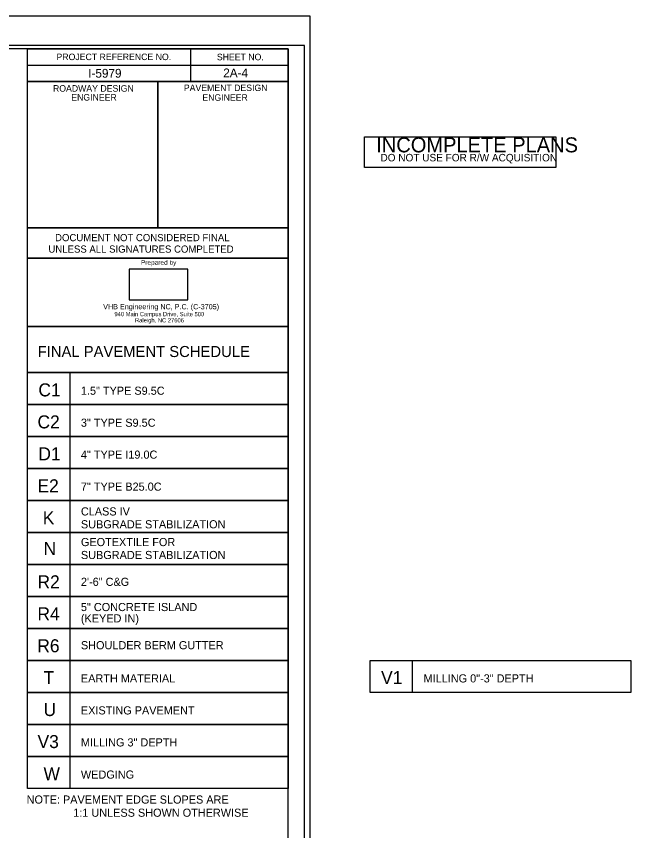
# Model space of a CAD drawing. Extents: x 573748 to 574632, y -54663 to -53209.
# Drawn here: x 574235.8 to 574330.2, y -54038.9 to -53913.7 of the extents above; entities that cross this region are included whole.
import ezdxf

# ---------------------------------------------------------------- set-up
doc = ezdxf.new("R2010")
doc.units = 0
for name, color, linetype in [('Default', 7, 'Continuous'), ('Prop Pavement Schedule Description CELL', 7, 'Continuous'), ('Sheet Cutting Line CELL', 7, 'Continuous'), ('Sheet Data Field CELL', 7, 'Continuous'), ('Sheet Plan CELL', 7, 'Continuous'), ('Sheet Plot Border Inside CELL', 7, 'Continuous'), ('Sheet Plot Border Outside CELL', 7, 'Continuous'), ('Sheet Sticker Exception Certification CELL', 7, 'Continuous'), ('Sheet Sticker Incomplete CELL', 7, 'Continuous'), ('Sheet Typical CELL', 7, 'Continuous')]:
    doc.layers.add(name, color=color, linetype=linetype)

msp = doc.modelspace()

# ---------------------------------------------------------------- linework, layer by layer
at = {"layer": 'Default'}
msp.add_lwpolyline([(574253.15, -53957.25), (574262.18, -53957.25), (574262.18, -53952.53), (574253.15, -53952.53)], close=True, dxfattribs=at)
at = {"layer": 'Prop Pavement Schedule Description CELL'}
msp.add_lwpolyline([(574237.56, -53961.37), (574277.57, -53961.37), (574277.57, -53968.45), (574237.56, -53968.45)], close=True, dxfattribs=at)
for points in [[(574244.08, -53973.37), (574237.56, -53973.37), (574237.56, -53968.45), (574277.57, -53968.45), (574277.57, -53973.37), (574244.08, -53973.37), (574244.08, -53968.45)], [(574244.08, -53978.28), (574237.56, -53978.28), (574237.56, -53973.37), (574277.57, -53973.37), (574277.57, -53978.28), (574244.08, -53978.28), (574244.08, -53973.37)], [(574244.08, -53983.2), (574237.56, -53983.2), (574237.56, -53978.28), (574277.57, -53978.28), (574277.57, -53983.2), (574244.08, -53983.2), (574244.08, -53978.28)], [(574244.08, -53988.12), (574237.56, -53988.12), (574237.56, -53983.2), (574277.57, -53983.2), (574277.57, -53988.12), (574244.08, -53988.12), (574244.08, -53983.2)], [(574244.08, -53993.04), (574237.56, -53993.04), (574237.56, -53988.12), (574277.57, -53988.12), (574277.57, -53993.04), (574244.08, -53993.04), (574244.08, -53988.12)], [(574244.08, -53997.96), (574237.56, -53997.96), (574237.56, -53993.04), (574277.57, -53993.04), (574277.57, -53997.96), (574244.08, -53997.96), (574244.08, -53993.04)], [(574244.08, -54002.88), (574237.56, -54002.88), (574237.56, -53997.96), (574277.57, -53997.96), (574277.57, -54002.88), (574244.08, -54002.88), (574244.08, -53997.96)], [(574244.08, -54007.79), (574237.56, -54007.79), (574237.56, -54002.88), (574277.57, -54002.88), (574277.57, -54007.79), (574244.08, -54007.79), (574244.08, -54002.88)], [(574244.08, -54012.71), (574237.56, -54012.71), (574237.56, -54007.79), (574277.57, -54007.79), (574277.57, -54012.71), (574244.08, -54012.71), (574244.08, -54007.79)], [(574244.08, -54017.63), (574237.56, -54017.63), (574237.56, -54012.71), (574277.57, -54012.71), (574277.57, -54017.63), (574244.08, -54017.63), (574244.08, -54012.71)], [(574296.7, -54017.63), (574290.19, -54017.63), (574290.19, -54012.71), (574330.19, -54012.71), (574330.19, -54017.63), (574296.7, -54017.63), (574296.7, -54012.71)], [(574244.08, -54022.55), (574237.56, -54022.55), (574237.56, -54017.63), (574277.57, -54017.63), (574277.57, -54022.55), (574244.08, -54022.55), (574244.08, -54017.63)], [(574244.08, -54027.47), (574237.56, -54027.47), (574237.56, -54022.55), (574277.57, -54022.55), (574277.57, -54027.47), (574244.08, -54027.47), (574244.08, -54022.55)], [(574244.08, -54032.39), (574237.56, -54032.39), (574237.56, -54027.47), (574277.57, -54027.47), (574277.57, -54032.39), (574244.08, -54032.39), (574244.08, -54027.47)]]:
    msp.add_lwpolyline(points, dxfattribs=at)
at = {"layer": 'Sheet Cutting Line CELL'}
msp.add_line((574280.97, -53913.67), (573944.17, -53913.67), dxfattribs=at)
at = {"layer": 'Sheet Plan CELL'}
msp.add_lwpolyline([(574237.56, -53950.88), (574277.57, -53950.88), (574277.57, -53961.37), (574237.56, -53961.37)], close=True, dxfattribs=at)
at = {"layer": 'Sheet Plot Border Inside CELL'}
msp.add_lwpolyline([(574280.07, -53918.16), (573946.77, -53918.16), (573946.77, -54129.18), (574280.07, -54129.18)], close=True, dxfattribs=at)
at = {"layer": 'Sheet Plot Border Outside CELL'}
msp.add_lwpolyline([(574280.97, -53913.67), (573944.17, -53913.67), (573944.17, -54133.67), (574280.97, -54133.67)], close=True, dxfattribs=at)
at = {"layer": 'Sheet Sticker Exception Certification CELL'}
for p, q in [((574237.56, -53950.88), (574237.56, -53946.18)), ((574237.56, -53946.18), (574277.57, -53946.18)), ((574277.57, -53946.18), (574277.57, -53950.88)), ((574277.57, -53950.88), (574237.56, -53950.88))]:
    msp.add_line(p, q, dxfattribs=at)
at = {"layer": 'Sheet Sticker Incomplete CELL'}
msp.add_lwpolyline([(574289.32, -53936.93), (574289.32, -53932.23), (574318.72, -53932.23), (574318.72, -53936.93)], close=True, dxfattribs=at)
at = {"layer": 'Sheet Typical CELL'}
for p, q in [((574262.57, -53918.68), (574262.57, -53923.68)), ((574237.56, -53921.18), (574277.57, -53921.18)), ((574257.57, -53923.68), (574257.57, -53946.17))]:
    msp.add_line(p, q, dxfattribs=at)
for points in [[(574277.57, -53918.67), (573977.57, -53918.67), (573977.57, -54128.67), (574277.57, -54128.67)], [(574237.56, -53918.67), (574277.57, -53918.67), (574277.57, -53923.68), (574237.56, -53923.68)], [(574237.56, -53923.68), (574257.57, -53923.68), (574257.57, -53946.18), (574237.56, -53946.18)], [(574257.57, -53923.68), (574277.57, -53923.68), (574277.57, -53946.18), (574257.57, -53946.18)]]:
    msp.add_lwpolyline(points, close=True, dxfattribs=at)

# ---------------------------------------------------------------- texts
at = {"layer": 'Default'}
for s, height, rotation, p in [('Prepared by', 0.7214, 360, (574254.98, -53951.88)), ('VHB Engineering NC, P.C. (C-3705)', 0.8, 359.9612, (574249.17, -53958.71)), ('940 Main Campus Drive, Suite 500', 0.6436, 359.9612, (574250.9, -53959.78)), ('Raleigh, NC 27606', 0.6436, 359.9612, (574254.06, -53960.73))]:
    msp.add_text(s, height=height, rotation=rotation, dxfattribs=at).set_placement(p)
at = {"layer": 'Prop Pavement Schedule Description CELL'}
for s, height, p in [('FINAL PAVEMENT SCHEDULE', 1.7, (574239.11, -53966.06)), ('C1', 2, (574239.22, -53972.11)), ('1.5" TYPE S9.5C', 1.25, (574245.75, -53971.86)), ('C2', 2, (574239.08, -53977.03)), ('3" TYPE S9.5C', 1.25, (574245.75, -53976.78)), ('D1', 2, (574239.22, -53981.94)), ('4" TYPE I19.0C', 1.25, (574245.75, -53981.69)), ('E2', 2, (574239.08, -53986.86)), ('7" TYPE B25.0C', 1.25, (574245.75, -53986.61)), ('CLASS IV', 1.25, (574245.75, -53990.42)), ('K', 2, (574239.89, -53991.78)), ('SUBGRADE STABILIZATION', 1.25, (574245.75, -53992.4)), ('N', 2, (574240.01, -53996.5)), ('GEOTEXTILE FOR', 1.25, (574245.75, -53995.13)), ('SUBGRADE STABILIZATION', 1.25, (574245.75, -53997.12)), ('R2', 2, (574239.08, -54001.62)), ('2\'-6" C&G', 1.25, (574245.75, -54001.24)), ('R4', 2, (574239.07, -54006.54)), ('5" CONCRETE ISLAND', 1.25, (574245.75, -54005.12)), ('(KEYED IN)', 1.25, (574245.75, -54006.86)), ('R6', 2, (574239.05, -54011.45)), ('SHOULDER BERM GUTTER', 1.25, (574245.75, -54010.99)), ('T', 2, (574240.01, -54016.34)), ('V1', 2, (574291.85, -54016.34)), ('EARTH MATERIAL', 1.25, (574245.75, -54016.09)), ('MILLING 0"-3" DEPTH', 1.25, (574298.38, -54016.09)), ('U', 2, (574240.01, -54021.26)), ('EXISTING PAVEMENT', 1.25, (574245.75, -54021.01)), ('V3', 2, (574239.09, -54026.18)), ('MILLING 3" DEPTH', 1.25, (574245.75, -54025.93)), ('W', 2, (574240.01, -54031.13)), ('WEDGING', 1.25, (574245.75, -54030.88)), ('NOTE: PAVEMENT EDGE SLOPES ARE', 1.25, (574237.42, -54034.72)), ('1:1 UNLESS SHOWN OTHERWISE', 1.25, (574244.57, -54036.74))]:
    msp.add_text(s, height=height, dxfattribs=at).set_placement(p)
at = {"layer": 'Sheet Data Field CELL'}
for s, p in [('I-5979', (574246.87, -53923.11)), ('2A-4', (574267.61, -53923.05))]:
    msp.add_text(s, height=1.35, dxfattribs=at).set_placement(p)
at = {"layer": 'Sheet Sticker Exception Certification CELL'}
for s, p in [('DOCUMENT NOT CONSIDERED FINAL', (574241.78, -53948.25)), ('UNLESS ALL SIGNATURES COMPLETED', (574240.76, -53950.01))]:
    msp.add_text(s, height=1.1, dxfattribs=at).set_placement(p)
at = {"layer": 'Sheet Sticker Incomplete CELL'}
for s, height, p in [('INCOMPLETE PLANS', 2.304, (574291.11, -53934.59)), ('DO NOT USE FOR R/W ACQUISITION', 1.152, (574291.76, -53935.98))]:
    msp.add_text(s, height=height, dxfattribs=at).set_placement(p)
at = {"layer": 'Sheet Typical CELL'}
for s, p in [('PROJECT REFERENCE NO.', (574242, -53920.41)), ('SHEET NO.', (574266.63, -53920.43)), ('ROADWAY DESIGN', (574241.46, -53925.26)), ('PAVEMENT DESIGN', (574261.56, -53925.17)), ('ENGINEER', (574244.27, -53926.63)), ('ENGINEER', (574264.4, -53926.66))]:
    msp.add_text(s, height=1, dxfattribs=at).set_placement(p)

doc.saveas('drawing.dxf')
